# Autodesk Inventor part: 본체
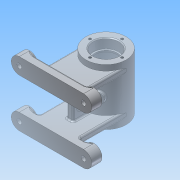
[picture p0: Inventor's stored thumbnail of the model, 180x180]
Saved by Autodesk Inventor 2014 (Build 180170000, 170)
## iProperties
Created: 2015-11
Part Number: 본체
Material: 알루미늄 6061
Document SubType Name: Modeling
Designer: net
Density: 2.71 g/cm^3
Appearance: 알루미늄 - 평지
Mass: 357.463 g
Surface Area: 461.435 cm^2
Volume: 131.905 cm^3
Author: net
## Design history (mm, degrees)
sketch "스케치1"
  geometry: C1 r 25 at (0, 0); 1 further point
  constraints: 1 centre point, 1 coincident
  dimensions: "d0" = 50 diameter of C1
extrude "돌출1" new body sketch "스케치1" stored distance "d1" = 70; taper "d2" = 0 deg
node "작업 평면1"
sketch "스케치2"
  geometry: L1 (-25, -35)-(25, -35) reference; L2 (25, 35)-(-25, 35) reference; L3 (40, -20)-(-40, -20); L4 (-40, -20)-(-40, -40); L5 (-40, -40)-(40, -40); L6 (40, -40)-(40, -20); L7 (40, 40)-(-40, 40); L8 (-40, 40)-(-40, 20); L9 (-40, 20)-(40, 20); L10 (40, 20)-(40, 40); 7 further points
  constraints: 16 end point, 6 midpoint, 6 vertical alignment, 4 parallel, 2 horizontal, 2 perpendicular, 8 other
  dimensions: "d4" = 40 distance from line of L5 point (0, 0); "d5" = 80 distance between parallel lines of L7 L5; "d6" = 20 distance of L7.end L8.end; "d7" = 20 distance of L3.end L4.end; "d8" = 80 distance of L4.end L5.end; "d9" = 80 distance of L7.start L7.end
  node "투영된 루프1"
extrude "돌출2" join sketch "스케치2" distance "d10" = 10; taper "d11" = 0 deg
extrude "돌출3" join sketch "스케치2" distance "d12" = 13; taper "d13" = 0 deg
node "작업 평면2"
sketch "스케치3"
  geometry: L1 (40, 40)-(-40, 40) reference; L2 (-40, 20)-(40, 20) reference; L3 (-40, -40)-(40, -40) reference; L4 (40, -20)-(-40, -20) reference; L5 (-25, 28)-(25, 28); L6 (25, 28)-(25, 20); L7 (25, 20)-(-25, 20); L8 (-25, 20)-(-25, 28); L9 (-25, -20)-(25, -20); L10 (25, -20)-(25, -28); L11 (25, -28)-(-25, -28); L12 (-25, -28)-(-25, -20); A1 r 10 centre (40, 30) between (40, 40) and (40, 20) reference; A2 r 10 centre (-40, 30) between (-40, 20) and (-40, 40) reference; A3 r 10 centre (-40, -30) between (-40, -40) and (-40, -20) reference; A4 r 10 centre (40, -30) between (40, -20) and (40, -40) reference; 5 further points
  constraints: 16 end point, 4 coincident, 4 midpoint, 4 parallel, 2 horizontal, 2 perpendicular
  dimensions: "d15" = 50 distance of L5.start L5.end; "d16" = 50 distance of L10.end L11.end; "d17" = 8 distance of L9.end L10.end; "d18" = 8 distance of L5.end L6.end
extrude "돌출4" join sketch "스케치3" stored distance "d19" = 13; taper "d20" = 0 deg
node "작업 평면3"
sketch "스케치4"
  geometry: L1 (-40, 20)-(40, 20) reference; L2 (40, -20)-(-40, -20) reference; L3 (4, 20)-(-4, 20); L4 (-4, 20)-(-4, -20); L5 (-4, -20)-(4, -20); L6 (4, -20)-(4, 20); 2 further points
  constraints: 8 end point, 2 parallel, 2 point on line, 1 horizontal, 1 midpoint, 1 perpendicular, 1 vertical alignment
  dimensions: "d22" = 8 distance between parallel lines of L4 L6
extrude "돌출5" join sketch "스케치4" stored distance "d23" = 13; taper "d24" = 0 deg
sketch "스케치5"
  geometry: L1 (-68, 40)-(-68, 20) reference; L2 (-24.678, 20)-(-24.678, -20) reference; L3 (-45, 20)-(-24.678, 20) reference; L4 (-45, 20)-(-45, -20) reference; L5 (-24.678, -20)-(-45, -20) reference; L6 (-31.5, 8)-(-31.5, -8); L7 (-38.5, 8)-(-38.5, -8); A1 r 3.5 centre (-35, 8) between (-31.5, 8) and (-38.5, 8); A2 r 3.5 centre (-35, -8) between (-38.5, -8) and (-31.5, -8); 2 further points
  constraints: 4 end point, 4 point on circle, 3 tangent, 2 centre point, 1 horizontal alignment, 1 midpoint, 1 parallel, 1 perpendicular
  dimensions: "d25" = 33 distance from line of A1.centre L1; "d26" = 7 diameter of A2; "d27" = 7 diameter of A1; "d28" = 16 distance of L7.start L7.end
extrude "돌출6" cut sketch "스케치5" stored distance "d29" = 13; taper "d30" = 0 deg
sketch "스케치6"
  geometry: L1 (25, 35)-(-25, 35) reference; L2 (25, -35)-(25, 35) reference; L3 (-25, -35)-(25, -35) reference; L4 (0, 62.563)-(0, -62.563); L5 (16, -35)-(16, -23); L6 (16, -23)-(14, -23); L7 (14, -23)-(14, -21); L8 (14, -21)-(21, -21); L9 (21, -21)-(21, 21); L10 (21, 21)-(14, 21); L11 (14, 21)-(14, 23); L12 (14, 23)-(16, 23); L13 (16, 23)-(16, 35); L14 (0, 35)-(16, 35); L15 (0, -35)-(16, -35); L16 (0, -35)-(0, 35); 3 further points
  constraints: 26 end point, 7 parallel, 4 midpoint, 4 point on line, 3 collinear, 3 perpendicular, 2 coincident, 1 horizontal alignment
  dimensions: "d31" = 32 diameter of L5 L4; "d32" = 28 diameter of L7 L4; "d33" = 32 diameter of L13 L4; "d34" = 28 diameter of L11 L4; "d35" = 42 diameter of L9 L4; "d36" = 12 distance of L5.start L5.end; "d37" = 12 distance of L12.end L13.end; "d38" = 42 distance of L8.end L9.end
revolve "회전1" sketch "스케치6" stored, may be unused: angle "d39" = 90 deg
node "작업 평면4"
sketch "스케치7"
  geometry: L1 (25, 35)-(-25, 35) reference; L2 (-25, -35)-(25, -35) reference; C1 r 5 at (0, 0); 1 further point
  constraints: 1 centre point, 1 coincident
  dimensions: "d41" = 10 diameter of C1
extrude "돌출7" join sketch "스케치7" stored distance "d42" = 13; taper "d43" = 0 deg
sketch "스케치8"
  geometry: L1 (0, 0)-(9.424, 0); L2 (0, 0)-(14, -24.249); L3 (0, 0)-(0, -8.439); C1 r 25 at (0, 0) reference; 1 further point
  constraints: 6 end point, 1 horizontal, 1 perpendicular
  dimensions: "d44" = 30 deg angle of L2 L3; "d45" = 28 distance of L1.start L2.end
node "작업 평면5"
sketch "스케치9"
  geometry: C1 r 6 at (0, 0); 1 further point
  constraints: 1 centre point, 1 coincident
  dimensions: "d46" = 12 diameter of C1
extrude "돌출8" join sketch "스케치9" stored distance "d47" = 13; taper "d48" = 0 deg
node "작업 평면6"
sketch "스케치10"
  geometry: 2 further points
  constraints: 2 coincident, 1 other
feature "엠보싱1" sketch "스케치10" dims "d4" = 40, "d5" = 80, "d6" = 20, "d7" = 20, "d8" = 80, "d9" = 80, "d49" = 0.5, "d50" = 0
fillet "모깎기1" dims "d51" = 0.3
chamfer "모따기1" distance "d52" = 1; stored, may be unused: second distance "d53" = 2, angle "d54" = 45 deg
fillet "모깎기2" dims "d55" = 3
fillet "모깎기3" dims "d56" = 2
fillet "모깎기4" dims "d57" = 2
fillet "모깎기5" dims "d58" = 2
fillet "모깎기6" dims "d59" = 2
fillet "모깎기7" dims "d60" = 2
fillet "모깎기8" dims "d61" = 2
fillet "모깎기9" dims "d62" = 2
hole "구멍1" diameter "d65" = 5.188; stored, may be unused: countersink angle "d69" = 90 deg, drill point angle "d71" = 118 deg; dims "d63" = 10, "d64" = 10, "d66" = 6, "d67" = 4, "d68" = 2, "d70" = 8
hole "구멍2" diameter "d74" = 5.188; stored, may be unused: countersink angle "d78" = 90 deg, drill point angle "d80" = 118 deg; dims "d72" = 10, "d73" = 10, "d75" = 6, "d76" = 4, "d77" = 2, "d79" = 8
sketch "스케치11"
  geometry: C1 r 25 at (0, 0) reference; 1 further point
  constraints: 1 vertical alignment
  dimensions: "d81" = 20 distance of C1.centre point (0, 20)
hole "구멍3" sketch "스케치11" at (0, 20) diameter "d82" = 3.242; stored, may be unused: countersink angle "d86" = 90 deg, drill point angle "d88" = 118 deg; dims "d83" = 8, "d84" = 4, "d85" = 2, "d87" = 10
sketch "스케치12"
  geometry: C1 r 25 at (0, 0) reference; 1 further point
  constraints: 1 vertical alignment
  dimensions: "d89" = 20 distance of C1.centre point (0, 20)
hole "구멍4" sketch "스케치12" at (0, 20) diameter "d90" = 3.242; stored, may be unused: countersink angle "d94" = 90 deg, drill point angle "d96" = 118 deg; dims "d91" = 8, "d92" = 4, "d93" = 2, "d95" = 10
hole "구멍5" diameter "d102" = 6; stored, may be unused: countersink angle "d106" = 90 deg, drill point angle "d108" = 118 deg; dims "d100" = 10, "d101" = 10, "d103" = 6, "d104" = 12, "d105" = 4, "d107" = 8
hole "구멍6" diameter "d111" = 6; stored, may be unused: countersink angle "d115" = 90 deg, drill point angle "d117" = 118 deg; dims "d109" = 10, "d110" = 10, "d112" = 6, "d113" = 12, "d114" = 4, "d116" = 8
hole "구멍7" diameter "d120" = 6; stored, may be unused: countersink angle "d124" = 90 deg, drill point angle "d126" = 118 deg; dims "d118" = 10, "d119" = 10, "d121" = 6, "d122" = 12, "d123" = 4, "d125" = 8
hole "구멍8" diameter "d129" = 6; stored, may be unused: countersink angle "d133" = 90 deg, drill point angle "d135" = 118 deg; dims "d127" = 10, "d128" = 10, "d130" = 6, "d131" = 12, "d132" = 4, "d134" = 8
fillet "모깎기10" dims "d136" = 0.3
chamfer "모따기2" distance "d137" = 1; stored, may be unused: second distance "d138" = 2, angle "d139" = 45 deg
node "솔리드1"
pattern_circular "원형 패턴1" dims angle "d98" = 360 deg
node "투영된 루프2"
node "투영된 루프3"
node "투영된 루프4"
other parameters: "d3" = -68, "d14" = -58, "d21" = -45, "d40" = 28
